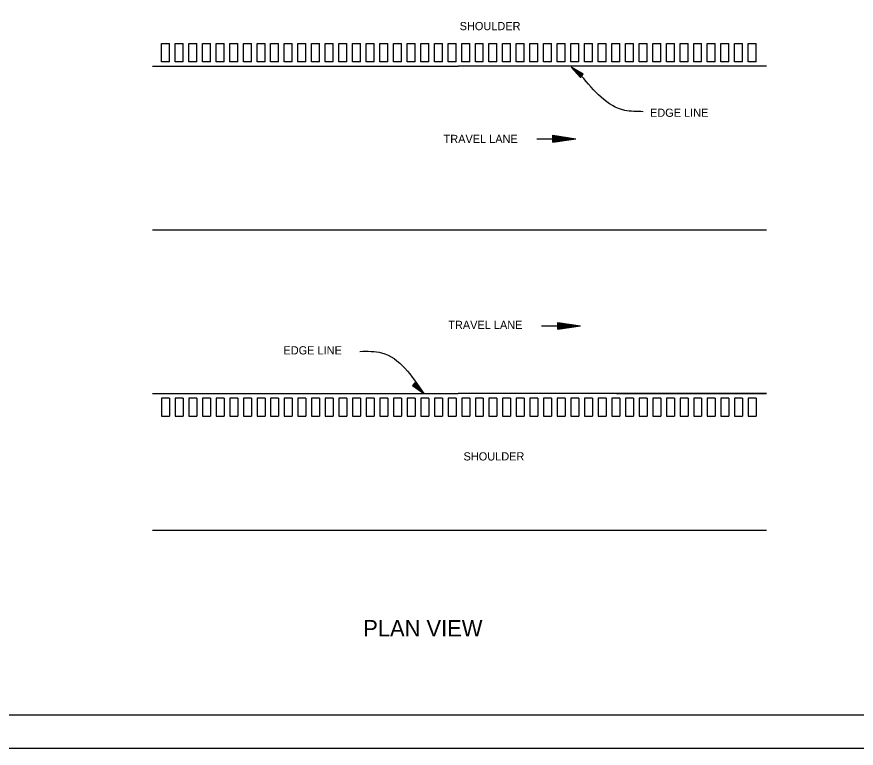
# Model space of a CAD drawing. Extents: x 1371343 to 1373043, y 378740 to 382040.
# Drawn here: x 1371912 to 1372541, y 378740 to 379289 of the extents above; entities that cross this region are included whole.
import ezdxf

# ---------------------------------------------------------------- set-up
doc = ezdxf.new("R2010")
doc.units = 0
doc.layers.add('E_Existing ROW', color=7, linetype='Continuous')
doc.layers.add('R_Border Notes', color=7, linetype='Continuous')

msp = doc.modelspace()

# ---------------------------------------------------------------- linework, layer by layer
at = {"layer": 'E_Existing ROW'}
for points in [[(1371342.92, 378740.49), (1373042.92, 378740.49), (1373042.92, 379840.49), (1371342.92, 379840.49)], [(1371367.92, 378765.49), (1373017.92, 378765.49), (1373017.92, 379815.49), (1371367.92, 379815.49)]]:
    msp.add_lwpolyline(points, close=True, dxfattribs=at)
at = {"layer": 'R_Border Notes'}
for p, q in [((1372020.39, 379255.47), (1372020.39, 379269.08)), ((1372020.39, 379269.08), (1372026.38, 379269.08)), ((1372026.38, 379255.47), (1372026.38, 379269.08)), ((1372030.62, 379255.47), (1372030.62, 379269.08)), ((1372030.62, 379269.08), (1372036.61, 379269.08)), ((1372036.61, 379255.47), (1372036.61, 379269.08)), ((1372040.86, 379255.47), (1372040.86, 379269.08)), ((1372040.86, 379269.08), (1372046.84, 379269.08)), ((1372046.84, 379255.47), (1372046.84, 379269.08)), ((1372051.09, 379255.47), (1372051.09, 379269.08)), ((1372051.09, 379269.08), (1372057.08, 379269.08)), ((1372057.08, 379255.47), (1372057.08, 379269.08)), ((1372061.32, 379255.47), (1372061.32, 379269.08)), ((1372061.32, 379269.08), (1372067.31, 379269.08)), ((1372067.31, 379255.47), (1372067.31, 379269.08)), ((1372071.56, 379255.47), (1372071.56, 379269.08)), ((1372071.56, 379269.08), (1372077.54, 379269.08)), ((1372077.54, 379255.47), (1372077.54, 379269.08)), ((1372081.79, 379255.47), (1372081.79, 379269.08)), ((1372081.79, 379269.08), (1372087.77, 379269.08)), ((1372087.77, 379255.47), (1372087.77, 379269.08)), ((1372092.02, 379255.47), (1372092.02, 379269.08)), ((1372092.02, 379269.08), (1372098.01, 379269.08)), ((1372098.01, 379255.47), (1372098.01, 379269.08)), ((1372102.25, 379255.47), (1372102.25, 379269.08)), ((1372102.25, 379269.08), (1372108.24, 379269.08)), ((1372108.24, 379255.47), (1372108.24, 379269.08)), ((1372112.49, 379255.47), (1372112.49, 379269.08)), ((1372112.49, 379269.08), (1372118.47, 379269.08)), ((1372118.47, 379255.47), (1372118.47, 379269.08)), ((1372122.72, 379255.47), (1372122.72, 379269.08)), ((1372122.72, 379269.08), (1372128.71, 379269.08)), ((1372128.71, 379255.47), (1372128.71, 379269.08)), ((1372132.95, 379255.47), (1372132.95, 379269.08)), ((1372132.95, 379269.08), (1372138.94, 379269.08)), ((1372138.94, 379255.47), (1372138.94, 379269.08)), ((1372143.18, 379255.47), (1372143.18, 379269.08)), ((1372143.18, 379269.08), (1372149.17, 379269.08)), ((1372149.17, 379255.47), (1372149.17, 379269.08)), ((1372153.42, 379255.47), (1372153.42, 379269.08)), ((1372153.42, 379269.08), (1372159.4, 379269.08)), ((1372159.4, 379255.47), (1372159.4, 379269.08)), ((1372163.65, 379255.47), (1372163.65, 379269.08)), ((1372163.65, 379269.08), (1372169.64, 379269.08)), ((1372169.64, 379255.47), (1372169.64, 379269.08)), ((1372173.88, 379255.47), (1372173.88, 379269.08)), ((1372173.88, 379255.47), (1372173.88, 379269.08)), ((1372173.88, 379269.08), (1372179.87, 379269.08)), ((1372179.87, 379255.47), (1372179.87, 379269.08)), ((1372184.12, 379255.47), (1372184.12, 379269.08)), ((1372184.12, 379269.08), (1372190.1, 379269.08)), ((1372190.1, 379255.47), (1372190.1, 379269.08)), ((1372194.35, 379255.47), (1372194.35, 379269.08)), ((1372194.35, 379269.08), (1372200.33, 379269.08)), ((1372200.33, 379255.47), (1372200.33, 379269.08)), ((1372204.58, 379255.47), (1372204.58, 379269.08)), ((1372204.58, 379269.08), (1372210.57, 379269.08)), ((1372210.57, 379255.47), (1372210.57, 379269.08)), ((1372214.81, 379255.47), (1372214.81, 379269.08)), ((1372214.81, 379269.08), (1372220.8, 379269.08)), ((1372220.8, 379255.47), (1372220.8, 379269.08)), ((1372225.05, 379255.47), (1372225.05, 379269.08)), ((1372225.05, 379269.08), (1372231.03, 379269.08)), ((1372231.03, 379255.47), (1372231.03, 379269.08)), ((1372235.28, 379255.47), (1372235.28, 379269.08)), ((1372235.28, 379269.08), (1372241.27, 379269.08)), ((1372241.27, 379255.47), (1372241.27, 379269.08)), ((1372245.51, 379255.47), (1372245.51, 379269.08)), ((1372245.51, 379269.08), (1372251.5, 379269.08)), ((1372251.5, 379255.47), (1372251.5, 379269.08)), ((1372255.75, 379255.47), (1372255.75, 379269.08)), ((1372255.75, 379269.08), (1372261.73, 379269.08)), ((1372261.73, 379255.47), (1372261.73, 379269.08)), ((1372265.98, 379255.47), (1372265.98, 379269.08)), ((1372265.98, 379269.08), (1372271.96, 379269.08)), ((1372271.96, 379255.47), (1372271.96, 379269.08)), ((1372276.21, 379255.47), (1372276.21, 379269.08)), ((1372276.21, 379269.08), (1372282.2, 379269.08)), ((1372282.2, 379255.47), (1372282.2, 379269.08)), ((1372286.44, 379255.47), (1372286.44, 379269.08)), ((1372286.44, 379269.08), (1372292.43, 379269.08)), ((1372292.43, 379255.47), (1372292.43, 379269.08)), ((1372296.68, 379255.47), (1372296.68, 379269.08)), ((1372296.68, 379269.08), (1372302.66, 379269.08)), ((1372302.66, 379255.47), (1372302.66, 379269.08)), ((1372306.91, 379255.47), (1372306.91, 379269.08)), ((1372306.91, 379269.08), (1372312.89, 379269.08)), ((1372312.89, 379255.47), (1372312.89, 379269.08)), ((1372317.14, 379255.47), (1372317.14, 379269.08)), ((1372317.14, 379269.08), (1372323.13, 379269.08)), ((1372323.13, 379255.47), (1372323.13, 379269.08)), ((1372327.37, 379255.47), (1372327.37, 379269.08)), ((1372327.37, 379269.08), (1372333.36, 379269.08)), ((1372333.36, 379255.47), (1372333.36, 379269.08)), ((1372337.61, 379255.47), (1372337.61, 379269.08)), ((1372337.61, 379269.08), (1372343.59, 379269.08)), ((1372343.59, 379255.47), (1372343.59, 379269.08)), ((1372347.84, 379255.47), (1372347.84, 379269.08)), ((1372347.84, 379269.08), (1372353.83, 379269.08)), ((1372353.83, 379255.47), (1372353.83, 379269.08)), ((1372358.07, 379255.47), (1372358.07, 379269.08)), ((1372358.07, 379269.08), (1372364.06, 379269.08)), ((1372364.06, 379255.47), (1372364.06, 379269.08)), ((1372368.31, 379255.47), (1372368.31, 379269.08)), ((1372368.31, 379269.08), (1372374.29, 379269.08)), ((1372374.29, 379255.47), (1372374.29, 379269.08)), ((1372378.54, 379255.47), (1372378.54, 379269.08)), ((1372378.54, 379269.08), (1372384.52, 379269.08)), ((1372384.52, 379255.47), (1372384.52, 379269.08)), ((1372388.77, 379255.47), (1372388.77, 379269.08)), ((1372388.77, 379269.08), (1372394.76, 379269.08)), ((1372394.76, 379255.47), (1372394.76, 379269.08)), ((1372399, 379255.47), (1372399, 379269.08)), ((1372399, 379269.08), (1372404.99, 379269.08)), ((1372404.99, 379255.47), (1372404.99, 379269.08)), ((1372409.24, 379255.47), (1372409.24, 379269.08)), ((1372409.24, 379269.08), (1372415.22, 379269.08)), ((1372415.22, 379255.47), (1372415.22, 379269.08)), ((1372419.47, 379255.47), (1372419.47, 379269.08)), ((1372419.47, 379269.08), (1372425.46, 379269.08)), ((1372425.46, 379255.47), (1372425.46, 379269.08)), ((1372429.7, 379255.47), (1372429.7, 379269.08)), ((1372429.7, 379269.08), (1372435.69, 379269.08)), ((1372435.69, 379255.47), (1372435.69, 379269.08)), ((1372439.93, 379255.47), (1372439.93, 379269.08)), ((1372439.93, 379269.08), (1372445.92, 379269.08)), ((1372445.92, 379255.47), (1372445.92, 379269.08)), ((1372450.17, 379255.47), (1372450.17, 379269.08)), ((1372450.17, 379269.08), (1372456.15, 379269.08)), ((1372456.15, 379255.47), (1372456.15, 379269.08)), ((1372460.4, 379255.47), (1372460.4, 379269.08)), ((1372460.4, 379269.08), (1372466.39, 379269.08)), ((1372466.39, 379255.47), (1372466.39, 379269.08)), ((1372013.74, 379252.06), (1372242.83, 379252.06)), ((1372026.38, 379255.47), (1372020.39, 379255.47)), ((1372036.61, 379255.47), (1372030.62, 379255.47)), ((1372046.84, 379255.47), (1372040.86, 379255.47)), ((1372057.08, 379255.47), (1372051.09, 379255.47)), ((1372067.31, 379255.47), (1372061.32, 379255.47)), ((1372077.54, 379255.47), (1372071.56, 379255.47)), ((1372087.77, 379255.47), (1372081.79, 379255.47)), ((1372098.01, 379255.47), (1372092.02, 379255.47)), ((1372108.24, 379255.47), (1372102.25, 379255.47)), ((1372118.47, 379255.47), (1372112.49, 379255.47)), ((1372128.71, 379255.47), (1372122.72, 379255.47)), ((1372138.94, 379255.47), (1372132.95, 379255.47)), ((1372149.17, 379255.47), (1372143.18, 379255.47)), ((1372159.4, 379255.47), (1372153.42, 379255.47)), ((1372169.64, 379255.47), (1372163.65, 379255.47)), ((1372179.87, 379255.47), (1372173.88, 379255.47)), ((1372190.1, 379255.47), (1372184.12, 379255.47)), ((1372200.33, 379255.47), (1372194.35, 379255.47)), ((1372210.57, 379255.47), (1372204.58, 379255.47)), ((1372220.8, 379255.47), (1372214.81, 379255.47)), ((1372231.03, 379255.47), (1372225.05, 379255.47)), ((1372241.27, 379255.47), (1372235.28, 379255.47)), ((1372474.06, 379252.06), (1372242.83, 379252.06)), ((1372251.5, 379255.47), (1372245.51, 379255.47)), ((1372261.73, 379255.47), (1372255.75, 379255.47)), ((1372271.96, 379255.47), (1372265.98, 379255.47)), ((1372282.2, 379255.47), (1372276.21, 379255.47)), ((1372292.43, 379255.47), (1372286.44, 379255.47)), ((1372302.66, 379255.47), (1372296.68, 379255.47)), ((1372312.89, 379255.47), (1372306.91, 379255.47)), ((1372323.13, 379255.47), (1372317.14, 379255.47)), ((1372333.36, 379255.47), (1372327.37, 379255.47)), ((1372334.56, 379243.67), (1372327.53, 379251.27)), ((1372336.48, 379246.08), (1372327.53, 379251.27)), ((1372334.72, 379243.88), (1372328.86, 379250.2)), ((1372336.33, 379245.87), (1372328.86, 379250.2)), ((1372343.59, 379255.47), (1372337.61, 379255.47)), ((1372353.83, 379255.47), (1372347.84, 379255.47)), ((1372364.06, 379255.47), (1372358.07, 379255.47)), ((1372374.29, 379255.47), (1372368.31, 379255.47)), ((1372384.52, 379255.47), (1372378.54, 379255.47)), ((1372394.76, 379255.47), (1372388.77, 379255.47)), ((1372404.99, 379255.47), (1372399, 379255.47)), ((1372415.22, 379255.47), (1372409.24, 379255.47)), ((1372425.46, 379255.47), (1372419.47, 379255.47)), ((1372435.69, 379255.47), (1372429.7, 379255.47)), ((1372445.92, 379255.47), (1372439.93, 379255.47)), ((1372456.15, 379255.47), (1372450.17, 379255.47)), ((1372466.39, 379255.47), (1372460.4, 379255.47)), ((1372336.15, 379245.67), (1372330.24, 379249.12)), ((1372334.9, 379244.08), (1372330.24, 379249.12)), ((1372335.05, 379244.29), (1372331.57, 379248.05)), ((1372336, 379245.46), (1372331.57, 379248.05)), ((1372335.82, 379245.26), (1372332.93, 379246.95)), ((1372335.2, 379244.49), (1372332.93, 379246.95)), ((1372335.66, 379245.05), (1372334.26, 379245.9)), ((1372335.36, 379244.7), (1372334.26, 379245.9)), ((1372334.56, 379243.67), (1372336.48, 379246.08)), ((1372313.82, 379200.26), (1372331.01, 379197.7)), ((1372313.82, 379195.12), (1372313.82, 379200.26)), ((1372313.82, 379199.85), (1372328.14, 379197.7)), ((1372301.74, 379197.7), (1372331.01, 379197.7)), ((1372313.82, 379199.39), (1372325.2, 379197.7)), ((1372313.82, 379198.98), (1372322.36, 379197.7)), ((1372313.82, 379198.55), (1372319.42, 379197.7)), ((1372313.82, 379198.11), (1372316.55, 379197.7)), ((1372313.82, 379195.12), (1372331.01, 379197.7)), ((1372313.82, 379196.88), (1372319.42, 379197.7)), ((1372313.82, 379195.96), (1372325.2, 379197.7)), ((1372313.82, 379195.55), (1372328.14, 379197.7)), ((1372313.82, 379196.42), (1372322.36, 379197.7)), ((1372313.82, 379197.27), (1372316.55, 379197.7)), ((1372013.74, 379129.27), (1372474.06, 379129.27)), ((1372305.43, 379057.41), (1372334.69, 379057.41)), ((1372317.5, 379059.94), (1372334.69, 379057.41)), ((1372317.5, 379054.83), (1372317.5, 379059.94)), ((1372317.5, 379059.53), (1372331.83, 379057.41)), ((1372317.5, 379059.1), (1372328.88, 379057.41)), ((1372317.5, 379058.66), (1372326.04, 379057.41)), ((1372317.5, 379058.23), (1372323.1, 379057.41)), ((1372317.5, 379057.82), (1372320.24, 379057.41)), ((1372317.5, 379054.83), (1372334.69, 379057.41)), ((1372317.5, 379056.57), (1372323.1, 379057.41)), ((1372317.5, 379055.67), (1372328.88, 379057.41)), ((1372317.5, 379055.24), (1372331.83, 379057.41)), ((1372317.5, 379056.11), (1372326.04, 379057.41)), ((1372317.5, 379056.98), (1372320.24, 379057.41)), ((1372210.72, 379014.79), (1372208.6, 379012.59)), ((1372208.6, 379012.59), (1372217.01, 379006.55)), ((1372208.78, 379012.77), (1372215.79, 379007.76)), ((1372208.96, 379012.95), (1372214.51, 379008.98)), ((1372209.13, 379013.13), (1372213.3, 379010.16)), ((1372209.31, 379013.31), (1372212.05, 379011.36)), ((1372209.49, 379013.51), (1372210.82, 379012.57)), ((1372209.83, 379013.85), (1372210.82, 379012.57)), ((1372210, 379014.02), (1372212.05, 379011.36)), ((1372210.18, 379014.23), (1372213.3, 379010.16)), ((1372210.36, 379014.41), (1372214.51, 379008.98)), ((1372210.54, 379014.59), (1372215.79, 379007.76)), ((1372210.72, 379014.79), (1372217.01, 379006.55)), ((1372013.74, 379006.48), (1372242.83, 379006.48)), ((1372474.06, 379006.48), (1372242.83, 379006.48)), ((1372361.65, 379006.48), (1372474.06, 379006.48)), ((1372026.38, 379003.08), (1372020.39, 379003.08)), ((1372020.39, 379003.08), (1372020.39, 378989.47)), ((1372026.38, 379003.08), (1372026.38, 378989.47)), ((1372036.61, 379003.08), (1372030.62, 379003.08)), ((1372030.62, 379003.08), (1372030.62, 378989.47)), ((1372036.61, 379003.08), (1372036.61, 378989.47)), ((1372046.84, 379003.08), (1372040.86, 379003.08)), ((1372040.86, 379003.08), (1372040.86, 378989.47)), ((1372046.84, 379003.08), (1372046.84, 378989.47)), ((1372057.08, 379003.08), (1372051.09, 379003.08)), ((1372051.09, 379003.08), (1372051.09, 378989.47)), ((1372057.08, 379003.08), (1372057.08, 378989.47)), ((1372067.31, 379003.08), (1372061.32, 379003.08)), ((1372061.32, 379003.08), (1372061.32, 378989.47)), ((1372067.31, 379003.08), (1372067.31, 378989.47)), ((1372077.54, 379003.08), (1372071.56, 379003.08)), ((1372071.56, 379003.08), (1372071.56, 378989.47)), ((1372077.54, 379003.08), (1372077.54, 378989.47)), ((1372087.77, 379003.08), (1372081.79, 379003.08)), ((1372081.79, 379003.08), (1372081.79, 378989.47)), ((1372087.77, 379003.08), (1372087.77, 378989.47)), ((1372098.01, 379003.08), (1372092.02, 379003.08)), ((1372092.02, 379003.08), (1372092.02, 378989.47)), ((1372098.01, 379003.08), (1372098.01, 378989.47)), ((1372108.24, 379003.08), (1372102.25, 379003.08)), ((1372102.25, 379003.08), (1372102.25, 378989.47)), ((1372108.24, 379003.08), (1372108.24, 378989.47)), ((1372118.47, 379003.08), (1372112.49, 379003.08)), ((1372112.49, 379003.08), (1372112.49, 378989.47)), ((1372118.47, 379003.08), (1372118.47, 378989.47)), ((1372128.71, 379003.08), (1372122.72, 379003.08)), ((1372122.72, 379003.08), (1372122.72, 378989.47)), ((1372128.71, 379003.08), (1372128.71, 378989.47)), ((1372138.94, 379003.08), (1372132.95, 379003.08)), ((1372132.95, 379003.08), (1372132.95, 378989.47)), ((1372138.94, 379003.08), (1372138.94, 378989.47)), ((1372149.17, 379003.08), (1372143.18, 379003.08)), ((1372143.18, 379003.08), (1372143.18, 378989.47)), ((1372149.17, 379003.08), (1372149.17, 378989.47)), ((1372159.4, 379003.08), (1372153.42, 379003.08)), ((1372153.42, 379003.08), (1372153.42, 378989.47)), ((1372159.4, 379003.08), (1372159.4, 378989.47)), ((1372169.64, 379003.08), (1372163.65, 379003.08)), ((1372163.65, 379003.08), (1372163.65, 378989.47)), ((1372169.64, 379003.08), (1372169.64, 378989.47)), ((1372179.87, 379003.08), (1372173.88, 379003.08)), ((1372173.88, 379003.08), (1372173.88, 378989.47)), ((1372179.87, 379003.08), (1372179.87, 378989.47)), ((1372190.1, 379003.08), (1372184.12, 379003.08)), ((1372184.12, 379003.08), (1372184.12, 378989.47)), ((1372190.1, 379003.08), (1372190.1, 378989.47)), ((1372200.33, 379003.08), (1372194.35, 379003.08)), ((1372194.35, 379003.08), (1372194.35, 378989.47)), ((1372200.33, 379003.08), (1372200.33, 378989.47)), ((1372210.57, 379003.08), (1372204.58, 379003.08)), ((1372204.58, 379003.08), (1372204.58, 378989.47)), ((1372210.57, 379003.08), (1372210.57, 378989.47)), ((1372220.8, 379003.08), (1372214.81, 379003.08)), ((1372214.81, 379003.08), (1372214.81, 378989.47)), ((1372220.8, 379003.08), (1372220.8, 378989.47)), ((1372231.03, 379003.08), (1372225.05, 379003.08)), ((1372225.05, 379003.08), (1372225.05, 378989.47)), ((1372231.03, 379003.08), (1372231.03, 378989.47)), ((1372241.27, 379003.08), (1372235.28, 379003.08)), ((1372235.28, 379003.08), (1372235.28, 378989.47)), ((1372241.27, 379003.08), (1372241.27, 378989.47)), ((1372251.5, 379003.08), (1372245.51, 379003.08)), ((1372245.51, 379003.08), (1372245.51, 378989.47)), ((1372251.5, 379003.08), (1372251.5, 378989.47)), ((1372261.73, 379003.08), (1372255.75, 379003.08)), ((1372255.75, 379003.08), (1372255.75, 378989.47)), ((1372261.73, 379003.08), (1372261.73, 378989.47)), ((1372271.96, 379003.08), (1372265.98, 379003.08)), ((1372265.98, 379003.08), (1372265.98, 378989.47)), ((1372271.96, 379003.08), (1372271.96, 378989.47)), ((1372282.2, 379003.08), (1372276.21, 379003.08)), ((1372276.21, 379003.08), (1372276.21, 378989.47)), ((1372282.2, 379003.08), (1372282.2, 378989.47)), ((1372292.43, 379003.08), (1372286.44, 379003.08)), ((1372286.44, 379003.08), (1372286.44, 378989.47)), ((1372292.43, 379003.08), (1372292.43, 378989.47)), ((1372302.66, 379003.08), (1372296.68, 379003.08)), ((1372296.68, 379003.08), (1372296.68, 378989.47)), ((1372302.66, 379003.08), (1372302.66, 378989.47)), ((1372312.89, 379003.08), (1372306.91, 379003.08)), ((1372306.91, 379003.08), (1372306.91, 378989.47)), ((1372312.89, 379003.08), (1372312.89, 378989.47)), ((1372323.13, 379003.08), (1372317.14, 379003.08)), ((1372317.14, 379003.08), (1372317.14, 378989.47)), ((1372323.13, 379003.08), (1372323.13, 378989.47)), ((1372333.36, 379003.08), (1372327.37, 379003.08)), ((1372327.37, 379003.08), (1372327.37, 378989.47)), ((1372333.36, 379003.08), (1372333.36, 378989.47)), ((1372343.59, 379003.08), (1372337.61, 379003.08)), ((1372337.61, 379003.08), (1372337.61, 378989.47)), ((1372343.59, 379003.08), (1372343.59, 378989.47)), ((1372353.83, 379003.08), (1372347.84, 379003.08)), ((1372347.84, 379003.08), (1372347.84, 378989.47)), ((1372353.83, 379003.08), (1372353.83, 378989.47)), ((1372364.06, 379003.08), (1372358.07, 379003.08)), ((1372358.07, 379003.08), (1372358.07, 378989.47)), ((1372364.06, 379003.08), (1372364.06, 378989.47)), ((1372374.29, 379003.08), (1372368.31, 379003.08)), ((1372368.31, 379003.08), (1372368.31, 378989.47)), ((1372374.29, 379003.08), (1372374.29, 378989.47)), ((1372384.52, 379003.08), (1372378.54, 379003.08)), ((1372378.54, 379003.08), (1372378.54, 378989.47)), ((1372384.52, 379003.08), (1372384.52, 378989.47)), ((1372394.76, 379003.08), (1372388.77, 379003.08)), ((1372388.77, 379003.08), (1372388.77, 378989.47)), ((1372394.76, 379003.08), (1372394.76, 378989.47)), ((1372404.99, 379003.08), (1372399, 379003.08)), ((1372399, 379003.08), (1372399, 378989.47)), ((1372404.99, 379003.08), (1372404.99, 378989.47)), ((1372415.22, 379003.08), (1372409.24, 379003.08)), ((1372409.24, 379003.08), (1372409.24, 378989.47)), ((1372415.22, 379003.08), (1372415.22, 378989.47)), ((1372425.46, 379003.08), (1372419.47, 379003.08)), ((1372419.47, 379003.08), (1372419.47, 378989.47)), ((1372425.46, 379003.08), (1372425.46, 378989.47)), ((1372435.69, 379003.08), (1372429.7, 379003.08)), ((1372429.7, 379003.08), (1372429.7, 378989.47)), ((1372435.69, 379003.08), (1372435.69, 378989.47)), ((1372445.92, 379003.08), (1372439.93, 379003.08)), ((1372439.93, 379003.08), (1372439.93, 378989.47)), ((1372445.92, 379003.08), (1372445.92, 378989.47)), ((1372456.15, 379003.08), (1372450.17, 379003.08)), ((1372450.17, 379003.08), (1372450.17, 378989.47)), ((1372456.15, 379003.08), (1372456.15, 378989.47)), ((1372466.39, 379003.08), (1372460.4, 379003.08)), ((1372460.4, 379003.08), (1372460.4, 378989.47)), ((1372466.39, 379003.08), (1372466.39, 378989.47)), ((1372020.39, 378989.47), (1372026.38, 378989.47)), ((1372030.62, 378989.47), (1372036.61, 378989.47)), ((1372040.86, 378989.47), (1372046.84, 378989.47)), ((1372051.09, 378989.47), (1372057.08, 378989.47)), ((1372061.32, 378989.47), (1372067.31, 378989.47)), ((1372071.56, 378989.47), (1372077.54, 378989.47)), ((1372081.79, 378989.47), (1372087.77, 378989.47)), ((1372092.02, 378989.47), (1372098.01, 378989.47)), ((1372102.25, 378989.47), (1372108.24, 378989.47)), ((1372112.49, 378989.47), (1372118.47, 378989.47)), ((1372122.72, 378989.47), (1372128.71, 378989.47)), ((1372132.95, 378989.47), (1372138.94, 378989.47)), ((1372143.18, 378989.47), (1372149.17, 378989.47)), ((1372153.42, 378989.47), (1372159.4, 378989.47)), ((1372163.65, 378989.47), (1372169.64, 378989.47)), ((1372173.88, 378989.47), (1372179.87, 378989.47)), ((1372184.12, 378989.47), (1372190.1, 378989.47)), ((1372194.35, 378989.47), (1372200.33, 378989.47)), ((1372204.58, 378989.47), (1372210.57, 378989.47)), ((1372214.81, 378989.47), (1372220.8, 378989.47)), ((1372225.05, 378989.47), (1372231.03, 378989.47)), ((1372235.28, 378989.47), (1372241.27, 378989.47)), ((1372245.51, 378989.47), (1372251.5, 378989.47)), ((1372255.75, 378989.47), (1372261.73, 378989.47)), ((1372265.98, 378989.47), (1372271.96, 378989.47)), ((1372276.21, 378989.47), (1372282.2, 378989.47)), ((1372286.44, 378989.47), (1372292.43, 378989.47)), ((1372296.68, 378989.47), (1372302.66, 378989.47)), ((1372306.91, 378989.47), (1372312.89, 378989.47)), ((1372317.14, 378989.47), (1372323.13, 378989.47)), ((1372327.37, 378989.47), (1372333.36, 378989.47)), ((1372337.61, 378989.47), (1372343.59, 378989.47)), ((1372347.84, 378989.47), (1372353.83, 378989.47)), ((1372358.07, 378989.47), (1372364.06, 378989.47)), ((1372368.31, 378989.47), (1372374.29, 378989.47)), ((1372378.54, 378989.47), (1372384.52, 378989.47)), ((1372388.77, 378989.47), (1372394.76, 378989.47)), ((1372399, 378989.47), (1372404.99, 378989.47)), ((1372409.24, 378989.47), (1372415.22, 378989.47)), ((1372419.47, 378989.47), (1372425.46, 378989.47)), ((1372429.7, 378989.47), (1372435.69, 378989.47)), ((1372439.93, 378989.47), (1372445.92, 378989.47)), ((1372450.17, 378989.47), (1372456.15, 378989.47)), ((1372460.4, 378989.47), (1372466.39, 378989.47)), ((1372013.74, 378904.15), (1372474.06, 378904.15))]:
    msp.add_line(p, q, dxfattribs=at)
for points in [[(1372381.61, 379218.01), (1372367.74, 379219.01), (1372335.15, 379244.98)], [(1372169.18, 379038.22), (1372185.47, 379037.1), (1372217.01, 379006.55)]]:
    msp.add_spline(points, degree=3, dxfattribs=at)

# ---------------------------------------------------------------- texts
for s, height, p in [('SHOULDER', 6.14, (1372243.98, 379279.15)), ('EDGE LINE', 6.14, (1372386.7, 379214.15)), ('TRAVEL LANE', 6.1396, (1372231.92, 379194.5)), ('TRAVEL LANE', 6.1396, (1372235.43, 379054.98)), ('EDGE LINE', 6.14, (1372111.86, 379035.9)), ('SHOULDER', 6.14, (1372246.89, 378956.36)), ('PLAN VIEW ', 12.279, (1372171.67, 378824.37))]:
    msp.add_text(s, height=height, dxfattribs=at).set_placement(p)

doc.saveas('drawing.dxf')
